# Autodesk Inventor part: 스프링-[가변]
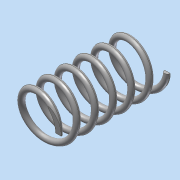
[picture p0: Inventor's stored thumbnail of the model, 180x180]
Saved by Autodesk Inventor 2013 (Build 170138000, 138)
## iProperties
Created: 2017-06
Part Number: 스프링-[가변]
Material: 강철, 연강
Document SubType Name: Modeling
Designer: Administrator
Density: 7.86 g/cm^3
Mass: 7.31543 g
Surface Area: 18.9743 cm^2
Volume: 0.930716 cm^3
Author: Administrator
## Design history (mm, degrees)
sketch "스케치1"
  geometry: L1 (0, 0)-(8, 0); L2 (8, 0)-(8, 38); L3 (8, 38)-(0, 38); L4 (0, 38)-(0, 0); C1 r 1 at (8, 0)
  constraints: 8 end point, 2 parallel, 1 centre point, 1 coincident, 1 horizontal, 1 perpendicular
  dimensions: "d0" = 38 distance of L1.end L2.end (derived); "d2" = 16 diameter of L2 L4; "d3" = 2 diameter of C1
feature "코일1" sketch "스케치1" pitch "d4" = 10; turns "d6" = 6; dims "d5" = 38 (= d0), "d7" = 0, angle "d8" = 90 deg, angle "d9" = 90 deg, "d10" = 0, "d11" = 0
sketch "스케치2"
  geometry: L1 (-15, 0)-(15, 0); L2 (15, 0)-(15, 38); L3 (15, 38)-(-15, 38); L4 (-15, 38)-(-15, 0); 7 further points
  constraints: 8 end point, 4 horizontal alignment, 2 horizontal, 2 midpoint, 2 vertical alignment, 1 parallel, 1 perpendicular
  dimensions: "d12" = 30 distance of L2.end L3.end
extrude "돌출1" sketch "스케치2" stored distance "d14" = 50; taper "d15" = 0 deg
node "솔리드1"
node "투영된 루프1"
